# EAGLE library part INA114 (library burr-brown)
Precision Instrumentation Amplifier
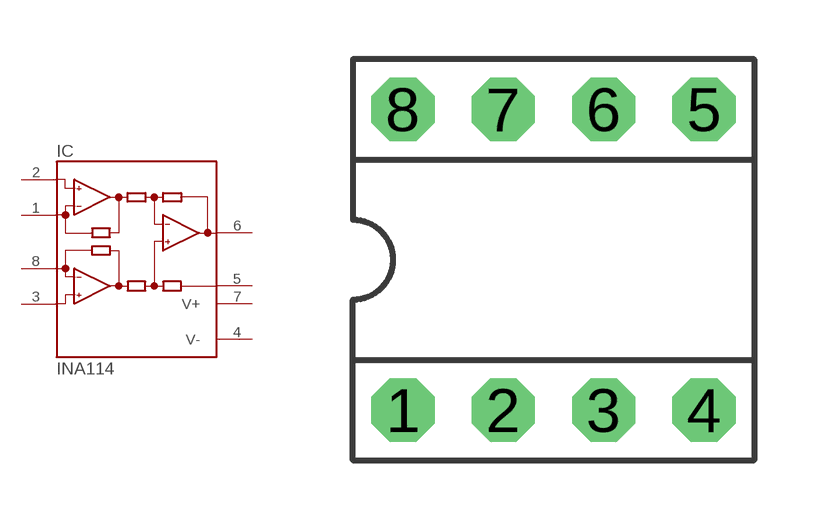
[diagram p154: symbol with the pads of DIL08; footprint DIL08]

Designator prefix IC

## INA114P (MF: TEXAS INSTRUMENTS; MPN: INA114BP; OC_FARNELL: 1212399; OC_NEWARK: 74K3810)  [DIL08]
1  RG  pas
2  -IN  in
3  +IN  in
4  V-  pwr
5  REF  pas
6  OUT  out
7  V+  pwr
8  RG  pas

## Footprint DIL08 (pad centres in mm)
Dual In Line
drill 0.813 pad 1.6 octagon: 1 -3.81,-3.81; 2 -1.27,-3.81; 3 1.27,-3.81; 4 3.81,-3.81; 5 3.81,3.81; 6 1.27,3.81; 7 -1.27,3.81; 8 -3.81,3.81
